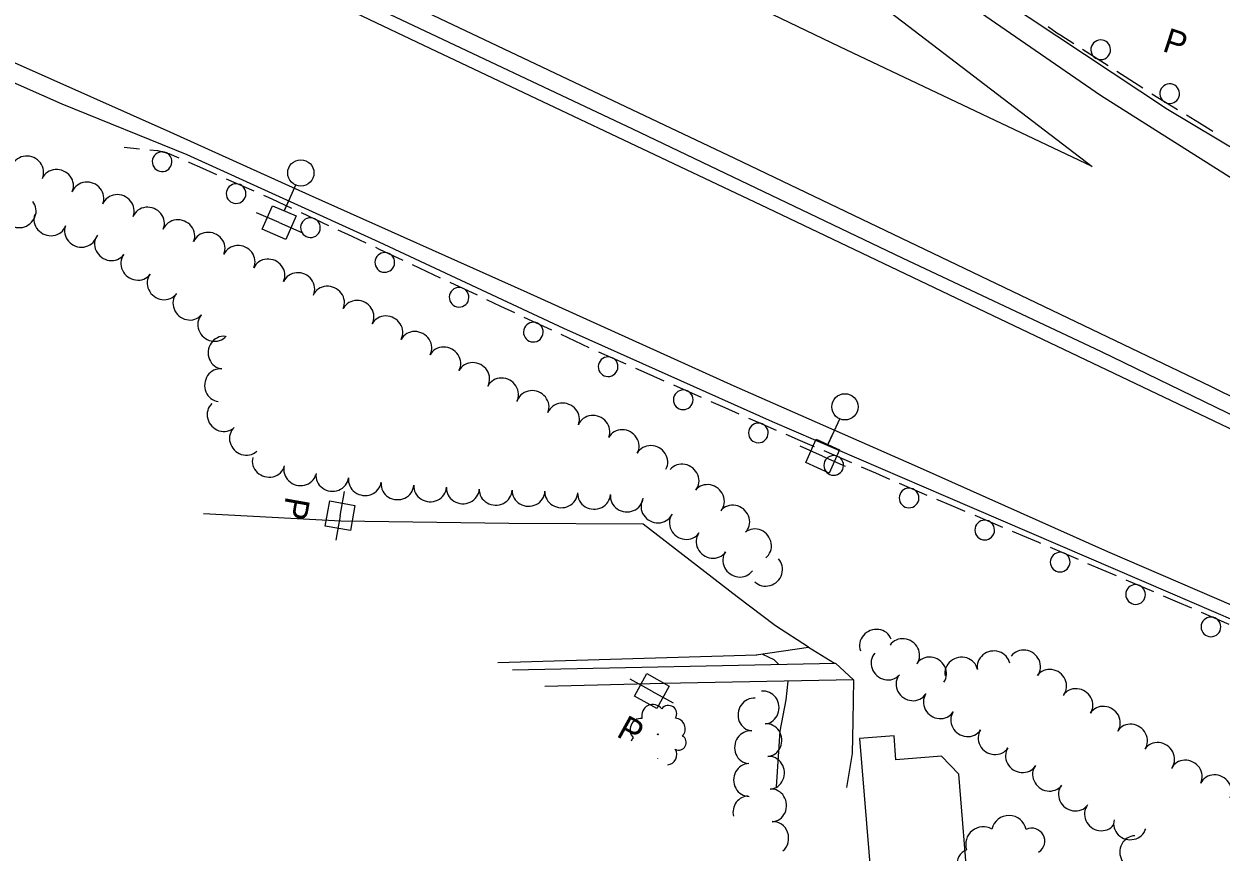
# Model space of a CAD drawing. Extents: x 1746010 to 1754829, y 655801 to 663091.
# Drawn here: x 1746343 to 1746707.7, y 662573.6 to 662825.9 of the extents above; entities that cross this region are included whole.
import ezdxf

# ---------------------------------------------------------------- set-up
doc = ezdxf.new("R2010")
doc.units = 0
for name, color, linetype in [('SURVEY - AERIAL SURVEY - Photo Control - Points - Locators', 7, 'Continuous'), ('SURVEY - AERIAL SURVEY - Photo Control - Points - Numbers', 7, 'Continuous'), ('SURVEY - CENTERLINE - Existing Roads - Development', 7, 'Continuous'), ('SURVEY - CENTERLINE - Existing Roads Curve Text', 7, 'Continuous'), ('SURVEY - CENTERLINE - Existing Roads Text', 7, 'Continuous')]:
    doc.layers.add(name, color=color, linetype=linetype)

msp = doc.modelspace()

# ---------------------------------------------------------------- linework, layer by layer
at = {"layer": 'SURVEY - AERIAL SURVEY - Photo Control - Points - Locators'}
for points in [[(1746929.72, 662652.27), (1746782.27, 662736.35), (1746720.09, 662772.98), (1746670.97, 662804.05), (1746617.8, 662840.77), (1746552.2, 662890.2), (1746497.41, 662932.37), (1746440.73, 662977), (1746415.88, 662996.18), (1746394.18, 663011.61), (1746373.15, 663024.15), (1746347.07, 663039.52)], [(1746329.9, 663029.57), (1746356.32, 663015.38), (1746389.32, 662995.68), (1746423.68, 662971.31), (1746455.04, 662946.71), (1746499.45, 662912.06), (1746551.2, 662872), (1746597.89, 662836.43), (1746668.43, 662782.45), (1746591.59, 662818.93), (1746524.93, 662850.97), (1746450.77, 662886.09), (1746389.56, 662915.38), (1746326.66, 662945.88), (1746264.04, 662974.74), (1746248.31, 662982.32)], [(1746937.59, 662657.19), (1746882.34, 662689.89), (1746809.95, 662731.33), (1746744.62, 662768.02), (1746691.33, 662799.82), (1746632.43, 662839.04), (1746574.22, 662880.88), (1746520.31, 662922.22), (1746450.33, 662976.48), (1746412.31, 663005.46)], [(1746201.3, 662955.1), (1746220.85, 662945.8), (1746338.42, 662890.3), (1746446.16, 662838.82), (1746559.49, 662784.93), (1746704.47, 662715.53), (1746795.84, 662670.36), (1746885.61, 662624.64)], [(1746569.48, 662769.79), (1746464.81, 662819.32), (1746363.57, 662867.48), (1746266.84, 662913.73), (1746218.78, 662936.42), (1746191.61, 662949.48)], [(1746114.66, 662904.92), (1746157.57, 662891.75), (1746193.26, 662877.89), (1746233.13, 662861.28), (1746267.38, 662846.61), (1746300.5, 662831.74), (1746339.16, 662814.51), (1746387.47, 662792.97), (1746429.89, 662773.86), (1746496.22, 662744.14), (1746559.32, 662715.65), (1746615.12, 662691.07), (1746673.07, 662665.19), (1746716.67, 662646.39), (1746754.01, 662630.08), (1746813.77, 662600.8), (1746832.3, 662591.25)], [(1746108.05, 662901.09), (1746144.78, 662887.93), (1746203.39, 662866.44), (1746249, 662847.4), (1746288.84, 662830.57), (1746354.56, 662801.49), (1746392.63, 662786.06), (1746451.14, 662759.5), (1746507.4, 662733.21), (1746570.91, 662704.8), (1746623.79, 662682.03), (1746692.22, 662652.56), (1746744.98, 662629.82), (1746795.1, 662605.98), (1746828.33, 662588.76)], [(1746876.9, 662619.18), (1746790.19, 662663.27), (1746716.47, 662699.65), (1746642.54, 662734.95), (1746569.48, 662769.79)], [(1746566.08, 662633.68), (1746581.98, 662636.07), (1746571.99, 662642.56), (1746560.32, 662651.41), (1746531.69, 662673.5), (1746490.75, 662673.68), (1746439.56, 662674.38), (1746397.69, 662676.66)], [(1746581.98, 662636.07), (1746589.89, 662631.13)], [(1746487.42, 662631.37), (1746566.24, 662633.68)], [(1746491.86, 662629.1), (1746590.21, 662631.13), (1746595.69, 662626.11), (1746537.71, 662624.94), (1746501.66, 662624.1)], [(1746567.96, 662633.96), (1746571.46, 662632.32), (1746573.03, 662630.78)], [(1746572.32, 662593.47), (1746573.42, 662610.47), (1746575.26, 662619.95), (1746575.78, 662625.71)], [(1746595.69, 662626.11), (1746595.53, 662613.5), (1746595.28, 662603.65), (1746593.64, 662593.27)]]:
    msp.add_lwpolyline(points, dxfattribs=at)
at = {"layer": 'SURVEY - AERIAL SURVEY - Photo Control - Points - Numbers'}
for points in [[(1746195.86, 662951.95), (1746218.27, 662941.19), (1746316.65, 662894.45), (1746389.22, 662860.05), (1746454.4, 662828.81), (1746528.45, 662793.92), (1746610.6, 662754.65), (1746671.13, 662726.1), (1746733.75, 662695.7), (1746789.4, 662668.49), (1746880.97, 662621.73)], [(1746658.88, 662822.31), (1746657.71, 662823.07), (1746654.99, 662824.95)], [(1746662.84, 662819.77), (1746658.88, 662822.31)], [(1746673.27, 662813.07), (1746665.53, 662818.04)], [(1746679.92, 662808.79), (1746675.96, 662811.33)], [(1746683.87, 662806.25), (1746679.92, 662808.79)], [(1746694.41, 662799.72), (1746686.59, 662804.5), (1746686.56, 662804.52)], [(1746701.15, 662795.6), (1746697.14, 662798.05)], [(1746705.16, 662793.15), (1746701.15, 662795.6)], [(1746373.55, 662788.3), (1746378.22, 662787.85)], [(1746381.4, 662787.54), (1746383.69, 662787.32), (1746387.14, 662786.41), (1746390.19, 662785.07)], [(1746393.11, 662783.78), (1746393.21, 662783.74), (1746397.42, 662781.89)], [(1746397.42, 662781.89), (1746401.72, 662780)], [(1746404.65, 662778.71), (1746413.07, 662775.02)], [(1746416.01, 662773.73), (1746417.46, 662773.09), (1746420.28, 662771.77)], [(1746420.28, 662771.77), (1746424.54, 662769.78)], [(1746427.43, 662768.42), (1746435.77, 662764.52)], [(1746438.67, 662763.17), (1746442.92, 662761.18)], [(1746442.92, 662761.18), (1746447.18, 662759.19)], [(1746450.08, 662757.83), (1746451.24, 662757.29), (1746458.41, 662753.92)], [(1746461.31, 662752.56), (1746465.56, 662750.57)], [(1746465.56, 662750.57), (1746469.82, 662748.57)], [(1746472.72, 662747.21), (1746481.04, 662743.31)], [(1746483.94, 662741.95), (1746488.2, 662739.95)], [(1746488.2, 662739.95), (1746492.45, 662737.95)], [(1746495.35, 662736.6), (1746503.68, 662732.69)], [(1746506.57, 662731.33), (1746510.83, 662729.33)], [(1746510.83, 662729.33), (1746515.09, 662727.34)], [(1746518, 662726.01), (1746526.41, 662722.29)], [(1746529.34, 662721), (1746533.64, 662719.1)], [(1746533.64, 662719.1), (1746537.94, 662717.21)], [(1746540.87, 662715.92), (1746549.29, 662712.2)], [(1746552.22, 662710.91), (1746556.52, 662709.01)], [(1746556.52, 662709.01), (1746560.82, 662707.12)], [(1746563.75, 662705.83), (1746566.88, 662704.44), (1746572.18, 662702.16)], [(1746575.12, 662700.89), (1746579.43, 662699.03)], [(1746579.43, 662699.03), (1746583.75, 662697.16)], [(1746586.69, 662695.9), (1746595.13, 662692.25)], [(1746598.07, 662690.98), (1746602.39, 662689.12)], [(1746602.39, 662689.12), (1746606.7, 662687.26)], [(1746609.64, 662685.99), (1746618.09, 662682.35)], [(1746621.03, 662681.1), (1746625.36, 662679.27)], [(1746625.36, 662679.27), (1746629.69, 662677.44)], [(1746632.64, 662676.2), (1746641.12, 662672.62)], [(1746644.07, 662671.38), (1746648.4, 662669.55)], [(1746648.4, 662669.55), (1746652.12, 662667.98), (1746652.73, 662667.72)], [(1746655.67, 662666.46), (1746664.12, 662662.83)], [(1746667.06, 662661.56), (1746671.38, 662659.71)], [(1746671.38, 662659.71), (1746675.7, 662657.85)], [(1746678.64, 662656.59), (1746687.09, 662652.96)], [(1746690.03, 662651.7), (1746694.35, 662649.84)], [(1746694.35, 662649.84), (1746698.67, 662647.99)], [(1746701.61, 662646.72), (1746710.06, 662643.09)]]:
    msp.add_lwpolyline(points, dxfattribs=at)
for centre, start, end in [((1746671.03, 662818), 350.1107, 350.0968), ((1746692.05, 662804.61), 351.3943, 351.3803), ((1746385.11, 662783.89), 188.1852, 188.1712), ((1746407.64, 662774.18), 179.2322, 179.2182), ((1746430.31, 662763.82), 177.8594, 177.8454), ((1746452.95, 662753.22), 177.7928, 177.7789), ((1746475.58, 662742.61), 177.7928, 177.7789), ((1746498.21, 662731.99), 177.7928, 177.7789), ((1746520.97, 662721.47), 179.1281, 179.1141), ((1746543.85, 662711.38), 179.1281, 179.1141), ((1746566.74, 662701.29), 179.5795, 179.5655), ((1746589.69, 662691.39), 179.5795, 179.5655), ((1746612.65, 662681.48), 179.5795, 179.5655), ((1746635.69, 662671.71), 180.04, 180.026), ((1746658.68, 662661.95), 179.6771, 179.6631), ((1746681.65, 662652.08), 179.6771, 179.6631), ((1746704.62, 662642.22), 179.6771, 179.6631)]:
    msp.add_arc(centre, 3, start, end, dxfattribs=at)
at = {"layer": 'SURVEY - CENTERLINE - Existing Roads - Development'}
msp.add_lwpolyline([(1746602.38, 662558.69), (1746630.75, 662560.99), (1746627.8, 662597.33), (1746622.54, 662602.85), (1746608.66, 662601.72), (1746608.07, 662609.06), (1746597.57, 662608.21), (1746601.07, 662565.09), (1746601.86, 662565.15), (1746602.38, 662558.69)], dxfattribs=at)
at = {"layer": 'SURVEY - CENTERLINE - Existing Roads Curve Text'}
for p, q in [((1746425.81, 662776.92), (1746422.33, 662768.95)), ((1746422.49, 662769.31), (1746423.77, 662772.24)), ((1746420.76, 662765.37), (1746413.89, 662768.38)), ((1746420.76, 662765.37), (1746427.64, 662762.37)), ((1746591.52, 662705.69), (1746587.93, 662697.76)), ((1746588.1, 662698.13), (1746589.42, 662701.04)), ((1746586.33, 662694.21), (1746579.49, 662697.3)), ((1746586.33, 662694.21), (1746593.16, 662691.12)), ((1746439.32, 662676.07), (1746440.64, 662683.45)), ((1746439.32, 662676.07), (1746438, 662668.68)), ((1746534.28, 662622.68), (1746527.72, 662626.31)), ((1746534.28, 662622.68), (1746540.84, 662619.05))]:
    msp.add_line(p, q, dxfattribs=at)
for points in [[(1746415.63, 662763.36), (1746418.75, 662770.51), (1746425.9, 662767.38), (1746422.78, 662760.24)], [(1746581.17, 662692.26), (1746584.38, 662699.37), (1746591.49, 662696.15), (1746588.28, 662689.05)], [(1746443.85, 662679.22), (1746442.47, 662671.54), (1746434.79, 662672.91), (1746436.17, 662680.59)], [(1746532.76, 662627.98), (1746539.58, 662624.21), (1746535.81, 662617.38), (1746528.98, 662621.16)]]:
    msp.add_lwpolyline(points, close=True, dxfattribs=at)
for centre in [(1746427.37, 662780.49), (1746593.12, 662709.24)]:
    msp.add_circle(centre, 4, dxfattribs=at)
at = {"layer": 'SURVEY - CENTERLINE - Existing Roads Text'}
msp.add_circle((1746536.13, 662609.49), 0.106, dxfattribs=at)
for centre, radius, start, end in [((1746534.62, 662615.16), 3.43, 37.8221, 193.6606), ((1746539.36, 662615.75), 2.53, 328.075, 143.0753), ((1746531.1, 662610.9), 3.45, 86.9263, 224.4506), ((1746541.21, 662611.16), 3.26, 317.9161, 84.7618), ((1746542.48, 662606.98), 2.3, 242.6291, 59.9482), ((1746530.89, 662606.46), 3.03, 137.8736, 161.9394), ((1746538.89, 662603.27), 3.03, 273.123, 33.4301), ((1746534.11, 662602.99), 2.08, 337.7889, 338.7354), ((1746538.89, 662603.27), 3.03, 200.0104, 201.0829), ((1746643.1, 662579.45), 5.32, 11.3383, 167.1768), ((1746635.26, 662575.97), 5.36, 60.4425, 197.9667), ((1746650.07, 662576.98), 3.93, 301.5912, 116.5915), ((1746631.89, 662569.94), 4.7, 111.3897, 268.1786)]:
    msp.add_arc(centre, radius, start, end, dxfattribs=at)
for centre, major_axis, start_param, end_param in [((1746344.07, 662780.87), (4.56, -2.05), 0, 3.141593), ((1746353.17, 662776.78), (4.56, -2.05), 0, 3.141593), ((1746362.4, 662772.95), (4.62, -1.91), 0, 3.141593), ((1746371.63, 662769.12), (4.62, -1.91), 0, 3.141593), ((1746341.85, 662768.63), (-3.84, -3.2), 0, 3.141593), ((1746380.86, 662765.29), (4.62, -1.91), 0, 3.141593), ((1746351.03, 662766.1), (-4.68, 1.75), 0, 3.141593), ((1746390.1, 662761.46), (4.62, -1.91), 0, 3.141593), ((1746360.37, 662762.6), (-4.68, 1.75), 0, 3.141593), ((1746399.33, 662757.64), (4.62, -1.91), 0, 3.141593), ((1746369.43, 662758.58), (-4.01, 2.98), 0, 3.141593), ((1746408.48, 662753.63), (4.55, -2.07), 0, 3.141593), ((1746377.44, 662752.63), (-4.01, 2.98), 0, 3.141593), ((1746417.56, 662749.49), (4.55, -2.07), 0, 3.141593), ((1746426.64, 662745.35), (4.55, -2.07), 0, 3.141593), ((1746385.45, 662746.67), (-4.01, 2.98), 0, 3.141593), ((1746393.28, 662740.51), (-3.8, 3.25), 0, 3.141593), ((1746435.72, 662741.22), (4.55, -2.07), 0, 3.141593), ((1746444.71, 662736.87), (4.41, -2.37), 0, 3.141593), ((1746400.84, 662734.03), (-3.8, 3.25), 0, 3.141593), ((1746453.52, 662732.14), (4.41, -2.37), 0, 3.141593), ((1746462.33, 662727.41), (4.41, -2.37), 0, 3.141593), ((1746403.83, 662725.74), (0.53, 4.97), 0, 3.141593), ((1746471.14, 662722.68), (4.41, -2.37), 0, 3.141593), ((1746479.95, 662717.95), (4.41, -2.37), 0, 3.141593), ((1746402.76, 662715.83), (0.53, 4.97), 0, 3.141593), ((1746488.76, 662713.22), (4.41, -2.37), 0, 3.141593), ((1746498.02, 662709.43), (4.63, -1.89), 0, 3.141593), ((1746507.28, 662705.65), (4.63, -1.89), 0, 3.141593), ((1746403.67, 662706.59), (-3.43, 3.64), 0, 3.141593), ((1746516.54, 662701.87), (4.63, -1.89), 0, 3.141593), ((1746410.49, 662699.35), (-3.43, 3.64), 0, 3.141593), ((1746525.49, 662697.5), (4.37, -2.42), 0, 3.141593), ((1746534.21, 662692.68), (4.37, -2.42), 0, 3.141593), ((1746417.57, 662692.55), (-4.83, 1.31), 0, 3.141593), ((1746427.15, 662689.96), (-4.83, 1.31), 0, 3.141593), ((1746436.95, 662688.24), (-4.96, 0.65), 0, 3.141593), ((1746543.78, 662686.97), (3.89, -3.15), 0, 3.141593), ((1746446.87, 662686.93), (-4.96, 0.65), 0, 3.141593), ((1746456.79, 662685.67), (-4.99, 0.31), 0, 3.141593), ((1746466.76, 662685.04), (-4.99, 0.31), 0, 3.141593), ((1746551.5, 662680.72), (3.89, -3.15), 0, 3.141593), ((1746476.74, 662684.41), (-4.99, 0.31), 0, 3.141593), ((1746486.72, 662683.99), (-5, 0.16), 0, 3.141593), ((1746496.72, 662683.67), (-5, 0.16), 0, 3.141593), ((1746506.71, 662683.23), (-5, 0.22), 0, 3.141593), ((1746516.7, 662682.79), (-5, 0.22), 0, 3.141593), ((1746526.65, 662681.93), (-4.97, 0.51), 0, 3.141593), ((1746535.93, 662678.67), (-4.44, 2.31), 0, 3.141593), ((1746559.22, 662674.47), (3.89, -3.15), 0, 3.141593), ((1746544.54, 662673.67), (-4.09, 2.88), 0, 3.141593), ((1746552.69, 662667.94), (-4.09, 2.88), 0, 3.141593), ((1746565.91, 662667.15), (3.08, -3.94), 0, 3.141593), ((1746560.83, 662662.21), (-4.09, 2.88), 0, 3.141593), ((1746569.26, 662659.47), (-3.59, -3.48), 0, 3.141593), ((1746602.53, 662636.72), (4.67, 1.79), 0, 3.141593), ((1746610.98, 662633.83), (4.13, -2.82), 0, 3.141593), ((1746605.96, 662630.91), (-3.76, 3.3), 0, 3.141593), ((1746638.39, 662630.17), (4.91, 0.95), 0, 3.141593), ((1746647.81, 662630.37), (4.01, -2.98), 0, 3.141593), ((1746619.16, 662628.24), (4.13, -2.82), 0, 3.141593), ((1746628.57, 662628.28), (4.91, 0.95), 0, 3.141593), ((1746613.59, 662624.53), (-4.18, 2.74), 0, 3.141593), ((1746655.77, 662624.46), (4.01, -2.98), 0, 3.141593), ((1746663.76, 662618.61), (4.2, -2.72), 0, 3.141593), ((1746565.25, 662615.5), (0.52, 4.97), 0, 3.141593), ((1746568.36, 662617.66), (0.64, -4.96), 0, 3.141593), ((1746621.93, 662619.06), (-4.18, 2.74), 0, 3.141593), ((1746630.27, 662613.59), (-4.18, 2.74), 0, 3.141593), ((1746672.09, 662613.22), (4.2, -2.72), 0, 3.141593), ((1746569.19, 662607.72), (0.39, -4.99), 0, 3.141593), ((1746680.38, 662607.77), (4.15, -2.79), 0, 3.141593), ((1746564.2, 662605.55), (0.52, 4.97), 0, 3.141593), ((1746638.61, 662608.12), (-4.18, 2.74), 0, 3.141593), ((1746646.96, 662602.65), (-4.18, 2.74), 0, 3.141593), ((1746688.64, 662602.21), (4.15, -2.79), 0, 3.141593), ((1746569.97, 662597.79), (0.39, -4.99), 0, 3.141593), ((1746697.02, 662596.86), (4.47, -2.24), 0, 3.141593), ((1746563.92, 662595.6), (-0.05, 5), 0, 3.141593), ((1746655.17, 662597.02), (-3.98, 3.03), 0, 3.141593), ((1746705.95, 662592.38), (4.47, -2.24), 0, 3.141593), ((1746663.07, 662590.98), (-3.98, 3.03), 0, 3.141593), ((1746563.72, 662585.69), (-0.05, 5), 0, 1.788654), ((1746570.64, 662587.85), (0.32, -4.99), 0, 3.141593), ((1746670.98, 662584.95), (-3.98, 3.03), 0, 3.141593), ((1746571.28, 662577.91), (0.32, -4.99), 0.608498, 3.141593), ((1746679.92, 662582.12), (-4.81, 1.37), 0, 3.141593), ((1746681.54, 662573.61), (-0.08, 5), 0, 3.141593)]:
    msp.add_ellipse(centre, major_axis=major_axis, ratio=0.940188, start_param=start_param, end_param=end_param, dxfattribs=at)

# ---------------------------------------------------------------- texts
at = {"layer": 'SURVEY - CENTERLINE - Existing Roads Curve Text'}
for rotation, p in [(341.8707, (1746689.53, 662817.68)), (259.8608, (1746422.84, 662682.16)), (331.065, (1746523.2, 662609.04))]:
    msp.add_text('P', height=7.48, rotation=rotation, dxfattribs=at).set_placement(p)

doc.saveas('drawing.dxf')
